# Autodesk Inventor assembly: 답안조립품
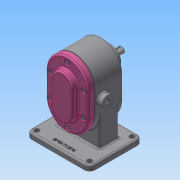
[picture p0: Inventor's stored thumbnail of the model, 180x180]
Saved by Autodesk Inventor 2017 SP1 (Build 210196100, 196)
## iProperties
Part Number: 답안조립품
Material: 일반
Document SubType Name: Assembly
Designer: 00-00
Author: 00-00
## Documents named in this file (11)
- C:\Users\00-00\Desktop\700906v1040\답안조립품.iam
- C:\Users\00-00\Desktop\700906v1040\본체.ipt
- C:\Users\00-00\Desktop\700906v1040\개스킷.ipt
- C:\Users\00-00\Desktop\700906v1040\메인축.ipt
- C:\Users\00-00\Desktop\700906v1040\베어링부시.ipt
- C:\Users\00-00\Desktop\700906v1040\볼트 M5.ipt
- C:\Users\00-00\Desktop\700906v1040\서브축.ipt
- C:\Users\00-00\Desktop\700906v1040\스퍼기어.ipt
- C:\Users\00-00\Desktop\700906v1040\오일 실 16 28 7.ipt
- C:\Users\00-00\Desktop\700906v1040\커버.ipt
- C:\Users\00-00\Desktop\700906v1040\키 6 x 6 x 18.ipt
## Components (1 placed, 1 different names)
1. 개스킷:1
